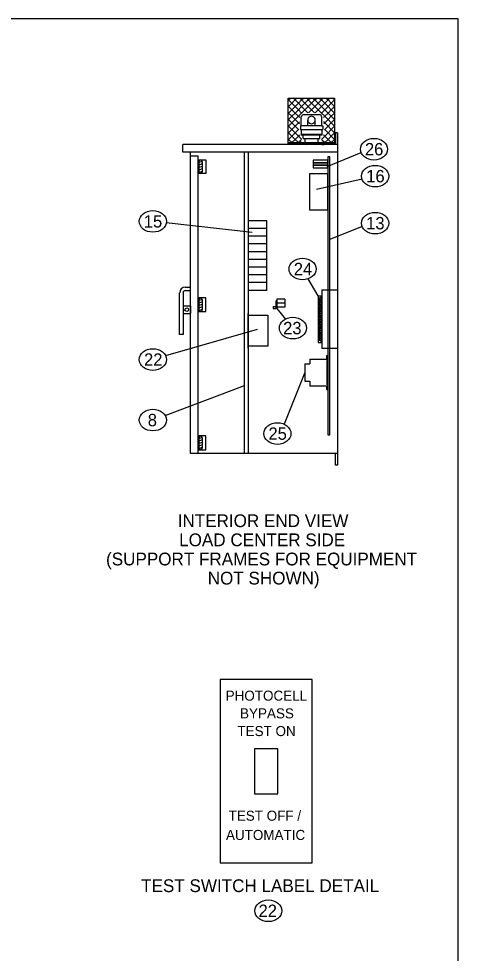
# Model space of a CAD drawing. Extents: x 99862 to 103680, y 99470 to 105076.
# Drawn here: x 102583 to 103151, y 103867 to 105076 of the extents above; entities that cross this region are included whole.
import ezdxf

# ---------------------------------------------------------------- set-up
doc = ezdxf.new("R2010")
doc.units = 0
for name, color, linetype in [('Level 1', 7, 'Continuous'), ('Level 15', 7, 'Continuous'), ('Level 20', 7, 'Continuous'), ('Level 40', 7, 'Continuous'), ('Level 60', 7, 'Continuous')]:
    doc.layers.add(name, color=color, linetype=linetype)

msp = doc.modelspace()

# ---------------------------------------------------------------- linework, layer by layer
at = {"layer": 'Level 1'}
for p, q in [((102931.3, 104972.9), (102991.3, 104972.9)), ((102931.3, 104915.2), (102931.3, 104972.9)), ((102931.3, 104970.7), (102931.5, 104970.5)), ((102931.5, 104970.5), (102931.3, 104970.3)), ((102931.5, 104970.5), (102934, 104972.9)), ((102935.8, 104966.2), (102931.5, 104970.5)), ((102931.5, 104962), (102935.8, 104966.2)), ((102940, 104970.5), (102935.8, 104966.2)), ((102935.8, 104966.2), (102940, 104962)), ((102940, 104970.5), (102937.6, 104972.9)), ((102942.5, 104972.9), (102940, 104970.5)), ((102944.3, 104966.2), (102940, 104970.5)), ((102940, 104962), (102944.3, 104966.2)), ((102948.5, 104970.5), (102944.3, 104966.2)), ((102944.3, 104966.2), (102948.5, 104962)), ((102946.1, 104972.9), (102948.5, 104970.5)), ((102948.5, 104970.5), (102951, 104972.9)), ((102952.8, 104966.2), (102948.5, 104970.5)), ((102948.5, 104962), (102952.8, 104966.2)), ((102957, 104970.5), (102952.8, 104966.2)), ((102952.8, 104966.2), (102957, 104962)), ((102954.6, 104972.9), (102957, 104970.5)), ((102957, 104970.5), (102959.5, 104972.9)), ((102961.3, 104966.2), (102957, 104970.5)), ((102957, 104962), (102961.3, 104966.2)), ((102965.6, 104970.5), (102961.3, 104966.2)), ((102961.3, 104966.2), (102965.6, 104962)), ((102963.1, 104972.9), (102965.6, 104970.5)), ((102965.6, 104970.5), (102968, 104972.9)), ((102969.8, 104966.2), (102965.6, 104970.5)), ((102965.6, 104962), (102969.8, 104966.2)), ((102974.1, 104970.5), (102969.8, 104966.2)), ((102969.8, 104966.2), (102974.1, 104962)), ((102971.6, 104972.9), (102974.1, 104970.5)), ((102974.1, 104970.5), (102976.5, 104972.9)), ((102978.3, 104966.2), (102974.1, 104970.5)), ((102974.1, 104962), (102978.3, 104966.2)), ((102982.6, 104970.5), (102978.3, 104966.2)), ((102978.3, 104966.2), (102982.6, 104962)), ((102980.1, 104972.9), (102982.6, 104970.5)), ((102985, 104972.9), (102982.6, 104970.5)), ((102982.6, 104970.5), (102986.8, 104966.2)), ((102986.8, 104966.2), (102982.6, 104962)), ((102986.8, 104966.2), (102991.1, 104970.5)), ((102991.1, 104962), (102986.8, 104966.2)), ((102991.1, 104970.5), (102988.6, 104972.9)), ((102991.3, 104970.7), (102991.1, 104970.5)), ((102991.1, 104970.5), (102991.3, 104970.3)), ((102991.3, 104915.2), (102991.3, 104972.9)), ((102931.3, 104962.2), (102931.5, 104962)), ((102931.5, 104962), (102931.3, 104961.8)), ((102931.3, 104953.7), (102931.5, 104953.5)), ((102931.5, 104953.5), (102931.3, 104953.2)), ((102935.8, 104957.7), (102931.5, 104962)), ((102931.5, 104953.5), (102935.8, 104957.7)), ((102935.8, 104949.2), (102931.5, 104953.5)), ((102940, 104962), (102935.8, 104957.7)), ((102935.8, 104957.7), (102940, 104953.5)), ((102940, 104953.5), (102935.8, 104949.2)), ((102944.3, 104957.7), (102940, 104962)), ((102940, 104953.5), (102944.3, 104957.7)), ((102944.3, 104949.2), (102940, 104953.5)), ((102948.5, 104962), (102944.3, 104957.7)), ((102944.3, 104957.7), (102948.5, 104953.5)), ((102948.5, 104953.5), (102944.3, 104949.2)), ((102952.8, 104957.7), (102948.5, 104962)), ((102948.5, 104953.5), (102952.8, 104957.7)), ((102948.8, 104953.3), (102948.5, 104953.5)), ((102957, 104962), (102952.8, 104957.7)), ((102952.8, 104957.7), (102956.7, 104953.8)), ((102961.3, 104957.7), (102957, 104962)), ((102957.4, 104953.8), (102961.3, 104957.7)), ((102965.6, 104962), (102961.3, 104957.7)), ((102961.3, 104957.7), (102965.2, 104953.8)), ((102969.8, 104957.7), (102965.6, 104962)), ((102965.9, 104953.8), (102969.8, 104957.7)), ((102974.1, 104962), (102969.8, 104957.7)), ((102969.8, 104957.7), (102974.1, 104953.5)), ((102974.1, 104953.5), (102973.8, 104953.3)), ((102978.3, 104957.7), (102974.1, 104962)), ((102974.1, 104953.5), (102978.3, 104957.7)), ((102978.3, 104949.2), (102974.1, 104953.5)), ((102982.6, 104962), (102978.3, 104957.7)), ((102978.3, 104957.7), (102982.6, 104953.5)), ((102982.6, 104953.5), (102978.3, 104949.2)), ((102982.6, 104962), (102986.8, 104957.7)), ((102986.8, 104957.7), (102982.6, 104953.5)), ((102982.6, 104953.5), (102986.8, 104949.2)), ((102986.8, 104957.7), (102991.1, 104962)), ((102991.1, 104953.5), (102986.8, 104957.7)), ((102986.8, 104949.2), (102991.1, 104953.5)), ((102991.3, 104962.2), (102991.1, 104962)), ((102991.1, 104962), (102991.3, 104961.8)), ((102991.3, 104953.7), (102991.1, 104953.5)), ((102991.1, 104953.5), (102991.3, 104953.2)), ((102931.3, 104945.2), (102931.5, 104945)), ((102931.5, 104945), (102931.3, 104944.7)), ((102931.5, 104945), (102935.8, 104949.2)), ((102935.8, 104940.7), (102931.5, 104945)), ((102935.8, 104949.2), (102940, 104945)), ((102940, 104945), (102935.8, 104940.7)), ((102940, 104945), (102944.3, 104949.2)), ((102944.3, 104940.7), (102940, 104945)), ((102944.3, 104949.2), (102945.7, 104947.8)), ((102945.7, 104942.1), (102944.3, 104940.7)), ((102948.1, 104937), (102948.1, 104948.2)), ((102951.3, 104951.4), (102971.3, 104951.4)), ((102956.5, 104937), (102956.5, 104944.4)), ((102966.1, 104937), (102966.1, 104944.4)), ((102974.5, 104937), (102974.5, 104948.2)), ((102976.9, 104947.8), (102978.3, 104949.2)), ((102978.3, 104940.7), (102976.9, 104942.1)), ((102978.3, 104949.2), (102982.6, 104945)), ((102982.6, 104945), (102978.3, 104940.7)), ((102986.8, 104949.2), (102982.6, 104945)), ((102982.6, 104945), (102986.8, 104940.7)), ((102991.1, 104945), (102986.8, 104949.2)), ((102986.8, 104940.7), (102991.1, 104945)), ((102991.3, 104945.2), (102991.1, 104945)), ((102991.1, 104945), (102991.3, 104944.7)), ((102931.3, 104936.7), (102931.5, 104936.5)), ((102931.5, 104936.5), (102931.3, 104936.2)), ((102931.5, 104936.5), (102935.8, 104940.7)), ((102935.8, 104932.2), (102931.5, 104936.5)), ((102931.5, 104927.9), (102935.8, 104932.2)), ((102935.8, 104940.7), (102940, 104936.5)), ((102940, 104936.5), (102935.8, 104932.2)), ((102935.8, 104932.2), (102940, 104927.9)), ((102940, 104936.5), (102944.3, 104940.7)), ((102944.3, 104932.2), (102940, 104936.5)), ((102940, 104927.9), (102944.3, 104932.2)), ((102944.3, 104940.7), (102945.6, 104939.4)), ((102944.5, 104932.4), (102944.3, 104932.2)), ((102944.3, 104932.2), (102944.5, 104932)), ((102948.1, 104937), (102946.9, 104937)), ((102946.9, 104937), (102946.9, 104932.2)), ((102946.9, 104932.2), (102975.7, 104932.2)), ((102974.5, 104937), (102948.1, 104937)), ((102948.1, 104932.2), (102948.1, 104925)), ((102974.5, 104937), (102975.7, 104937)), ((102974.5, 104932.2), (102974.5, 104925)), ((102975.7, 104937), (102975.7, 104932.2)), ((102977, 104939.4), (102978.3, 104940.7)), ((102978.3, 104932.2), (102978.1, 104932.4)), ((102978.1, 104932), (102978.3, 104932.2)), ((102978.3, 104940.7), (102982.6, 104936.5)), ((102982.6, 104936.5), (102978.3, 104932.2)), ((102978.3, 104932.2), (102982.6, 104927.9)), ((102986.8, 104940.7), (102982.6, 104936.5)), ((102982.6, 104936.5), (102986.8, 104932.2)), ((102986.8, 104932.2), (102982.6, 104927.9)), ((102991.1, 104936.5), (102986.8, 104940.7)), ((102986.8, 104932.2), (102991.1, 104936.5)), ((102991.1, 104927.9), (102986.8, 104932.2)), ((102991.3, 104936.7), (102991.1, 104936.5)), ((102991.1, 104936.5), (102991.3, 104936.2)), ((102931.3, 104928.2), (102931.5, 104927.9)), ((102931.5, 104927.9), (102931.3, 104927.7)), ((102931.3, 104919.7), (102931.5, 104919.4)), ((102931.5, 104919.4), (102931.3, 104919.2)), ((102935.8, 104923.7), (102931.5, 104927.9)), ((102931.5, 104919.4), (102935.8, 104923.7)), ((102935.8, 104915.2), (102931.5, 104919.4)), ((102940, 104927.9), (102935.8, 104923.7)), ((102935.8, 104923.7), (102940, 104919.4)), ((102940, 104919.4), (102935.8, 104915.2)), ((102944.3, 104923.7), (102940, 104927.9)), ((102940, 104919.4), (102944.3, 104923.7)), ((102944.3, 104915.2), (102940, 104919.4)), ((102945.7, 104925.1), (102944.3, 104923.7)), ((102944.3, 104923.7), (102948.2, 104919.7)), ((102948.4, 104919.3), (102944.3, 104915.2)), ((102974.5, 104925.6), (102948.1, 104925.6)), ((102974.5, 104925), (102948.1, 104925)), ((102950.5, 104920.8), (102950.5, 104925)), ((102971.5, 104920.2), (102951.1, 104920.2)), ((102952.9, 104915.3), (102952.9, 104920.2)), ((102969.7, 104915.3), (102969.7, 104920.2)), ((102972.1, 104920.8), (102972.1, 104925)), ((102978.3, 104915.2), (102974.2, 104919.3)), ((102974.4, 104919.7), (102978.3, 104923.7)), ((102978.3, 104923.7), (102976.9, 104925.1)), ((102982.6, 104927.9), (102978.3, 104923.7)), ((102978.3, 104923.7), (102982.6, 104919.4)), ((102982.6, 104919.4), (102978.3, 104915.2)), ((102982.6, 104927.9), (102986.8, 104923.7)), ((102986.8, 104923.7), (102982.6, 104919.4)), ((102982.6, 104919.4), (102986.8, 104915.2)), ((102986.8, 104923.7), (102991.1, 104927.9)), ((102991.1, 104919.4), (102986.8, 104923.7)), ((102986.8, 104915.2), (102991.1, 104919.4)), ((102991.3, 104928.2), (102991.1, 104927.9)), ((102991.1, 104927.9), (102991.3, 104927.7)), ((102991.3, 104919.7), (102991.1, 104919.4)), ((102991.1, 104919.4), (102991.3, 104919.2)), ((102931.3, 104915.2), (102991.3, 104915.2)), ((102931.3, 104914.1), (102931.3, 104915.1)), ((102931.3, 104915.1), (102991.3, 104915.1)), ((102931.3, 104914.1), (102991.3, 104914.1)), ((102967.3, 104912.9), (102955.3, 104912.9)), ((102991.3, 104914.1), (102991.3, 104915.1)), ((102814.8, 104875.1), (102814.8, 104892.9)), ((102874.8, 104512.9), (102874.8, 104902.9)), ((102879.8, 104512.9), (102879.8, 104902.9)), ((102984.8, 104897), (102982.2, 104897)), ((102982.2, 104897), (102982.2, 104724.9)), ((102984.8, 104724.9), (102984.8, 104897)), ((102815.8, 104890.9), (102815.8, 104877.1)), ((102819.8, 104890.9), (102815.8, 104889.3)), ((102819.8, 104887.7), (102815.8, 104886.1)), ((102819.8, 104884.4), (102815.8, 104882.9)), ((102819.8, 104881.2), (102815.8, 104879.7)), ((102819.8, 104890.9), (102819.8, 104877.1)), ((102819.8, 104878), (102815.9, 104876.5)), ((102903.6, 104814.1), (102879.8, 104814.1)), ((102903.6, 104724.1), (102903.6, 104814.1)), ((102903.6, 104804.1), (102879.8, 104804.1)), ((102903.6, 104794.1), (102879.8, 104794.1)), ((102903.6, 104784.1), (102879.8, 104784.1)), ((102903.6, 104774.1), (102879.8, 104774.1)), ((102903.6, 104764.1), (102879.8, 104764.1)), ((102903.6, 104754.1), (102879.8, 104754.1)), ((102903.6, 104744.1), (102879.8, 104744.1)), ((102798.1, 104728.2), (102804.8, 104728.2)), ((102798.1, 104723.7), (102804.8, 104723.7)), ((102903.6, 104734.1), (102879.8, 104734.1)), ((102903.6, 104724.1), (102879.8, 104724.1)), ((102974.8, 104724.9), (102974.8, 104648.7)), ((102974.8, 104724.9), (102994.8, 104724.9)), ((102982.2, 104724.9), (102982.2, 104648.7)), ((102984.8, 104648.7), (102984.8, 104724.9)), ((102790.8, 104666.9), (102790.8, 104720.9)), ((102795.2, 104720.9), (102795.2, 104666.9)), ((102814.8, 104714.3), (102814.8, 104696.6)), ((102815.8, 104712.3), (102815.8, 104698.6)), ((102819.8, 104712.3), (102815.8, 104710.8)), ((102819.8, 104712.3), (102819.8, 104698.6)), ((102926.9, 104712.5), (102916.5, 104712.5)), ((102916.5, 104712.5), (102916.5, 104702.5)), ((102926.9, 104712.5), (102926.9, 104702.5)), ((102969.8, 104716.8), (102969.8, 104656.8)), ((102969.8, 104716.8), (102974.8, 104716.8)), ((102973.5, 104716.8), (102973.5, 104656.8)), ((102974.8, 104716.8), (102974.8, 104656.8)), ((102795.2, 104704.1), (102804.8, 104704.1)), ((102804.8, 104704.1), (102804.8, 104694.1)), ((102819.8, 104709.1), (102815.8, 104707.6)), ((102819.8, 104705.9), (102815.8, 104704.4)), ((102819.8, 104702.7), (102815.8, 104701.1)), ((102819.8, 104699.5), (102815.9, 104698)), ((102911.5, 104703.1), (102911.5, 104700.6)), ((102911.5, 104703.1), (102915.3, 104703.1)), ((102911.5, 104700.6), (102915.3, 104700.6)), ((102915.3, 104710.6), (102915.3, 104700.6)), ((102915.3, 104710.6), (102916.5, 104710.6)), ((102916.5, 104700.6), (102915.3, 104700.6)), ((102916.5, 104710.6), (102916.5, 104700.6)), ((102926.9, 104707.5), (102916.5, 104707.5)), ((102926.9, 104702.5), (102916.5, 104702.5)), ((102795.2, 104694.1), (102804.8, 104694.1)), ((102879.8, 104694.3), (102879.1, 104694.3)), ((102879.1, 104694.3), (102879.1, 104649.3)), ((102879.8, 104649.3), (102879.8, 104694.3)), ((102795.2, 104666.9), (102790.8, 104666.9)), ((102969.8, 104656.8), (102974.8, 104656.8)), ((102879.8, 104649.3), (102879.1, 104649.3)), ((102994.8, 104648.7), (102974.8, 104648.7)), ((102980.5, 104639.6), (102980.5, 104635)), ((102980.5, 104639.6), (102982.2, 104639.6)), ((102982.2, 104648.7), (102982.2, 104537)), ((102982.2, 104639.6), (102982.2, 104634)), ((102984.8, 104610.4), (102984.8, 104648.7)), ((102952.8, 104628.9), (102952.8, 104606.5)), ((102952.8, 104628.9), (102959.2, 104628.9)), ((102959.2, 104635), (102959.2, 104628.9)), ((102959.2, 104635), (102980.5, 104635)), ((102982.1, 104634), (102980.9, 104632.9)), ((102980.9, 104632.9), (102980.9, 104602.5)), ((102952.8, 104606.5), (102959.2, 104606.5)), ((102959.2, 104606.5), (102959.2, 104600.4)), ((102982.2, 104601.4), (102980.9, 104602.5)), ((102984.8, 104537), (102984.8, 104610.4)), ((102959.2, 104600.4), (102980.5, 104600.4)), ((102980.5, 104600.4), (102980.5, 104595.8)), ((102980.5, 104595.8), (102982.2, 104595.8)), ((102982.2, 104601.4), (102982.2, 104595.8)), ((102814.8, 104535.8), (102814.8, 104518)), ((102815.8, 104533.8), (102815.8, 104520)), ((102819.8, 104533.8), (102815.8, 104532.2)), ((102819.8, 104530.6), (102815.8, 104529)), ((102819.8, 104533.8), (102819.8, 104520)), ((102982.2, 104537), (102984.8, 104537)), ((102819.8, 104527.4), (102815.8, 104525.8)), ((102819.8, 104524.1), (102815.8, 104522.6)), ((102819.8, 104520.9), (102815.9, 104519.4))]:
    msp.add_line(p, q, dxfattribs=at)
for points in [[(99862, 102999.5), (103151, 102999.5), (103151, 105075.5), (99862, 105075.5)], [(102963.4, 104889.2), (102982.2, 104889.2), (102982.2, 104892.4), (102963.4, 104892.4)], [(102963.4, 104885.9), (102982.2, 104885.9), (102982.2, 104889.2), (102963.4, 104889.2)], [(102963.4, 104882.7), (102982.2, 104882.7), (102982.2, 104885.9), (102963.4, 104885.9)], [(102982.2, 104874.9), (102958.7, 104874.9), (102958.7, 104828.2), (102982.2, 104828.2)], [(102879.8, 104691.8), (102904.8, 104691.8), (102904.8, 104651.8), (102879.8, 104651.8)], [(102961.9, 103983.4), (102961.9, 104220.5), (102843.4, 104220.5), (102843.4, 103983.4)], [(102887.7, 104131.1), (102887.7, 104072.8), (102917.6, 104072.8), (102917.6, 104131.1)]]:
    msp.add_lwpolyline(points, close=True, dxfattribs=at)
for points in [[(102814.8, 104892.9), (102824.8, 104892.9), (102824.8, 104875.1), (102814.8, 104875.1)], [(102814.8, 104696.6), (102824.8, 104696.6), (102824.8, 104714.3), (102814.8, 104714.3)], [(102814.8, 104518), (102824.8, 104518), (102824.8, 104535.8), (102814.8, 104535.8)]]:
    msp.add_lwpolyline(points, dxfattribs=at)
for centre, radius in [((102971.7, 104713.8), 0.758), ((102971.7, 104711.3), 0.758), ((102800, 104699.1), 2.37), ((102971.7, 104708.9), 0.758), ((102971.7, 104706.4), 0.758), ((102971.7, 104704), 0.758), ((102971.7, 104701.5), 0.758), ((102971.7, 104699.1), 0.758), ((102971.7, 104696.6), 0.758), ((102971.7, 104694.2), 0.758), ((102971.7, 104691.7), 0.758), ((102971.7, 104689.3), 0.758), ((102971.7, 104686.8), 0.758), ((102971.7, 104684.4), 0.758), ((102971.7, 104681.9), 0.758), ((102971.7, 104679.5), 0.758), ((102971.7, 104677), 0.758), ((102971.7, 104674.6), 0.758), ((102971.7, 104672.1), 0.758), ((102971.7, 104669.7), 0.758), ((102971.7, 104667.2), 0.758), ((102971.7, 104664.7), 0.758), ((102971.7, 104662.3), 0.758), ((102971.7, 104659.8), 0.758)]:
    msp.add_circle(centre, radius, dxfattribs=at)
for centre, radius, start, end in [((102951.3, 104948.2), 3.21, 90, 180), ((102961.3, 104944.4), 4.81, 0, 180.0003), ((102961.3, 104944.4), 4.81, 179.9997, 360), ((102971.3, 104948.2), 3.21, 0, 90), ((102951.1, 104920.8), 0.602, 180, 270), ((102971.5, 104920.8), 0.602, 270, 0), ((102955.3, 104915.3), 2.41, 180, 270), ((102967.3, 104915.3), 2.41, 270, 0), ((102817.8, 104890.9), 2, 90, 180), ((102817.8, 104890.9), 2, 0, 90), ((102817.8, 104877.1), 2, 180, 270), ((102817.8, 104877.1), 2, 270, 0), ((102798.1, 104720.9), 7.25, 90, 180), ((102798.1, 104720.9), 2.82, 90, 180), ((102817.8, 104712.3), 2, 90, 180), ((102817.8, 104712.3), 2, 0, 90), ((102817.8, 104698.6), 2, 180, 270), ((102817.8, 104698.6), 2, 270, 0), ((102817.8, 104533.8), 2, 90, 180), ((102817.8, 104533.8), 2, 0, 90), ((102817.8, 104520), 2, 180, 270), ((102817.8, 104520), 2, 270, 0)]:
    msp.add_arc(centre, radius, start, end, dxfattribs=at)
at = {"layer": 'Level 15'}
for p, q in [((102994.8, 104902.9), (102804.8, 104902.9)), ((102804.8, 104897.9), (102814.8, 104897.9)), ((102814.8, 104512.9), (102814.8, 104897.9)), ((102981.3, 104884.4), (103025.3, 104902.4)), ((103026.7, 104867.9), (102967.7, 104854.4)), ((102884.7, 104799.1), (102773.5, 104811.3)), ((103026.8, 104806.7), (102984.8, 104790)), ((102969.8, 104716.8), (102957.1, 104738.9)), ((102916.5, 104700.6), (102927.6, 104687)), ((102891.1, 104673.4), (102772.6, 104639.4)), ((102952.8, 104617.7), (102926, 104550.9)), ((102772, 104562.3), (102874.8, 104601.2)), ((102992.3, 104497.9), (102992.3, 104512.9)), ((102994.8, 104497.9), (102992.3, 104497.9))]:
    msp.add_line(p, q, dxfattribs=at)
at = {"layer": 'Level 20'}
for centre in [(103042, 104906.7), (103043.5, 104871.8), (102756.2, 104813.3), (103043.5, 104811), (102949.7, 104751.7), (102937.2, 104675.3), (102756.2, 104634.6), (102756.2, 104556.3), (102917.2, 104538.8), (102905.4, 103921.5)]:
    msp.add_ellipse(centre, major_axis=(-17.5, 0), ratio=0.8, dxfattribs=at)
at = {"layer": 'Level 40'}
for p, q in [((102994.8, 104927.9), (102992.3, 104927.9)), ((102992.3, 104927.9), (102992.3, 104912.9)), ((102994.8, 104927.9), (102994.8, 104497.9)), ((102994.8, 104912.9), (102794.8, 104912.9)), ((102794.8, 104902.9), (102794.8, 104912.9)), ((102804.8, 104902.9), (102794.8, 104902.9)), ((102804.8, 104512.9), (102804.8, 104902.9)), ((102994.8, 104512.9), (102804.8, 104512.9))]:
    msp.add_line(p, q, dxfattribs=at)
for points in [[(102948.2, 104913.3), (102948.2, 104913.2), (102945.5, 104913.2), (102945.5, 104913.3)], [(102948.2, 104913.2), (102948.2, 104912.9), (102945.5, 104912.9), (102945.5, 104913.2)], [(102947.8, 104915.1), (102947.8, 104915.9), (102945.9, 104915.9), (102945.9, 104915.1)], [(102947.8, 104913.3), (102947.8, 104914.1), (102945.9, 104914.1), (102945.9, 104913.3)], [(102974.4, 104913.3), (102974.4, 104913.2), (102977.1, 104913.2), (102977.1, 104913.3)], [(102974.4, 104913.2), (102974.4, 104912.9), (102977.1, 104912.9), (102977.1, 104913.2)], [(102974.8, 104915.1), (102974.8, 104915.9), (102976.7, 104915.9), (102976.7, 104915.1)], [(102974.8, 104913.3), (102974.8, 104914.1), (102976.7, 104914.1), (102976.7, 104913.3)]]:
    msp.add_lwpolyline(points, close=True, dxfattribs=at)
at = {"layer": 'Level 60'}
msp.add_line((103151, 105075.5), (103151, 105075.5), dxfattribs=at)

# ---------------------------------------------------------------- texts
at = {"layer": 'Level 20'}
for s, height, p in [('26', 16, (103030.3, 104898.7)), ('16', 16, (103032, 104863.8)), ('15', 16, (102744.5, 104805.3)), ('13', 16, (103031.9, 104803)), ('24', 16, (102938.4, 104743.7)), ('23', 16, (102924.6, 104667.3)), ('22', 16, (102744.8, 104626.6)), ('8', 16, (102749.6, 104548.3)), ('25', 16, (102905.6, 104530.8)), ('INTERIOR END VIEW', 16.5, (102788.3, 104417.8)), ('LOAD CENTER SIDE', 16.5, (102790.2, 104393.1)), ('(SUPPORT FRAMES FOR EQUIPMENT ', 16.5, (102695.7, 104368.3)), ('NOT SHOWN)', 16.5, (102827.1, 104343.6)), ('TEST SWITCH LABEL DETAIL', 16.5, (102741, 103945.7)), ('22', 16, (102892.8, 103913.5))]:
    msp.add_text(s, height=height, dxfattribs=at).set_placement(p)
at = {"layer": 'Level 40'}
for s, p in [('PHOTOCELL', (102850.3, 104193.3)), ('BYPASS', (102868.9, 104170.4)), ('TEST ON', (102865.5, 104147.5)), ('TEST OFF /', (102854.1, 104038)), ('AUTOMATIC', (102850.7, 104013.1))]:
    msp.add_text(s, height=13, dxfattribs=at).set_placement(p)

doc.saveas('drawing.dxf')
